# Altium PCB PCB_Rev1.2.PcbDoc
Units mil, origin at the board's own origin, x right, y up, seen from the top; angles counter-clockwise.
Board outline 1241 x 1329.22 mil, 4 copper layers (Top Layer, Layer 1, Layer 2, Bottom Layer), stack 69.556 mil thick; 69 components, 56 nets, 301 pads, 112 vias.
Unrouted connection lines stored in the file: 76.
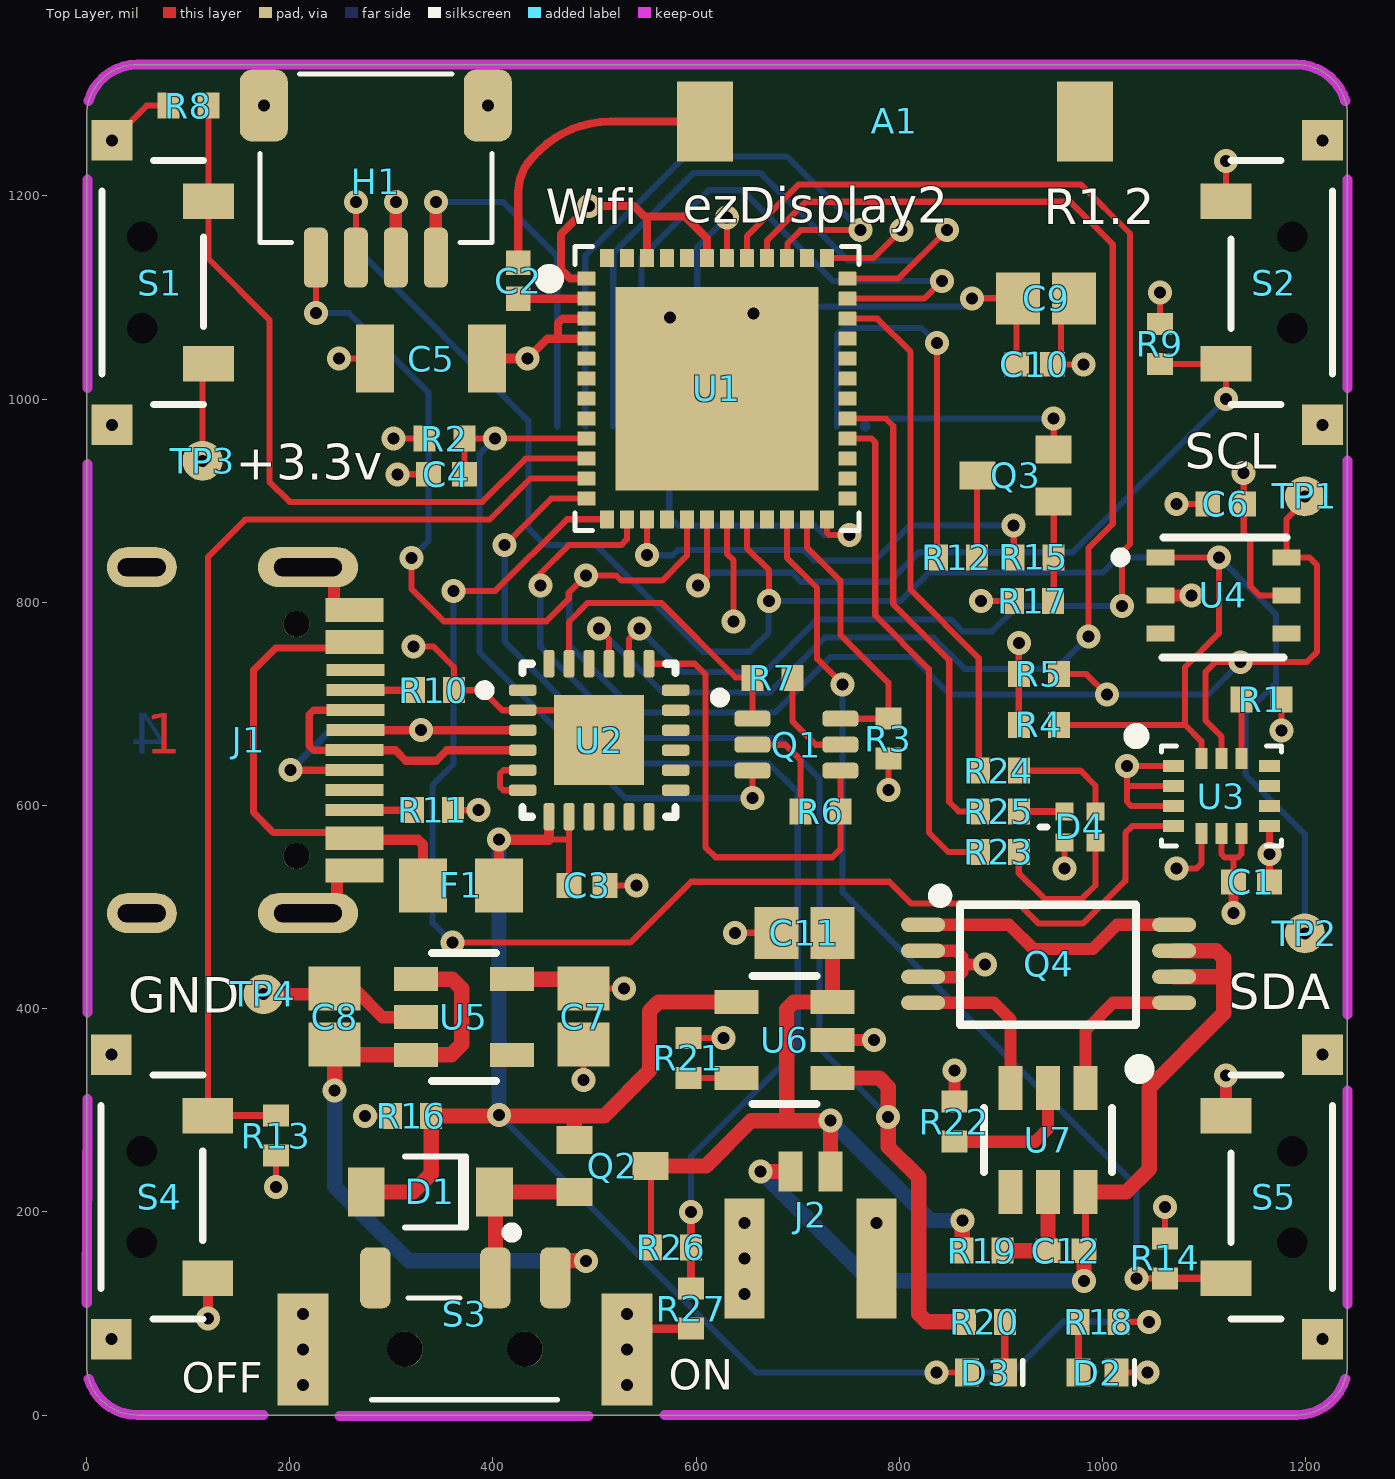
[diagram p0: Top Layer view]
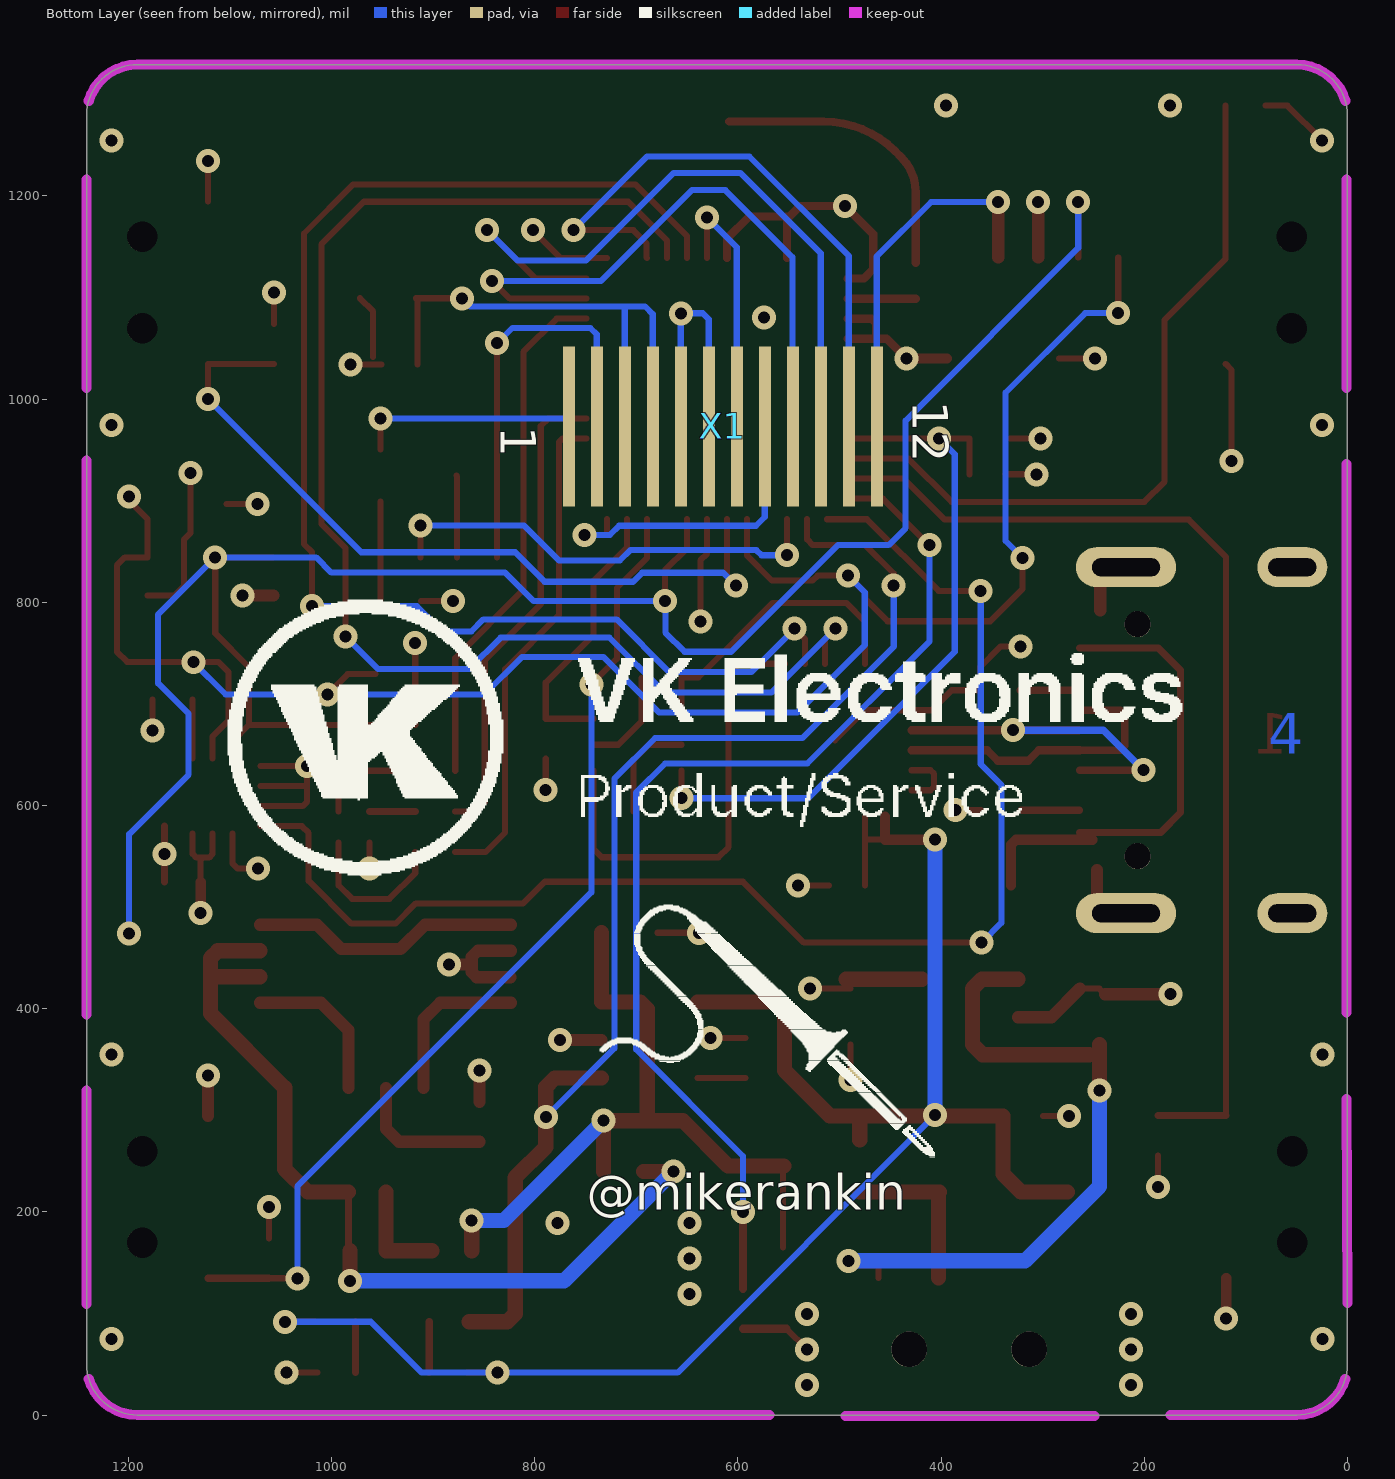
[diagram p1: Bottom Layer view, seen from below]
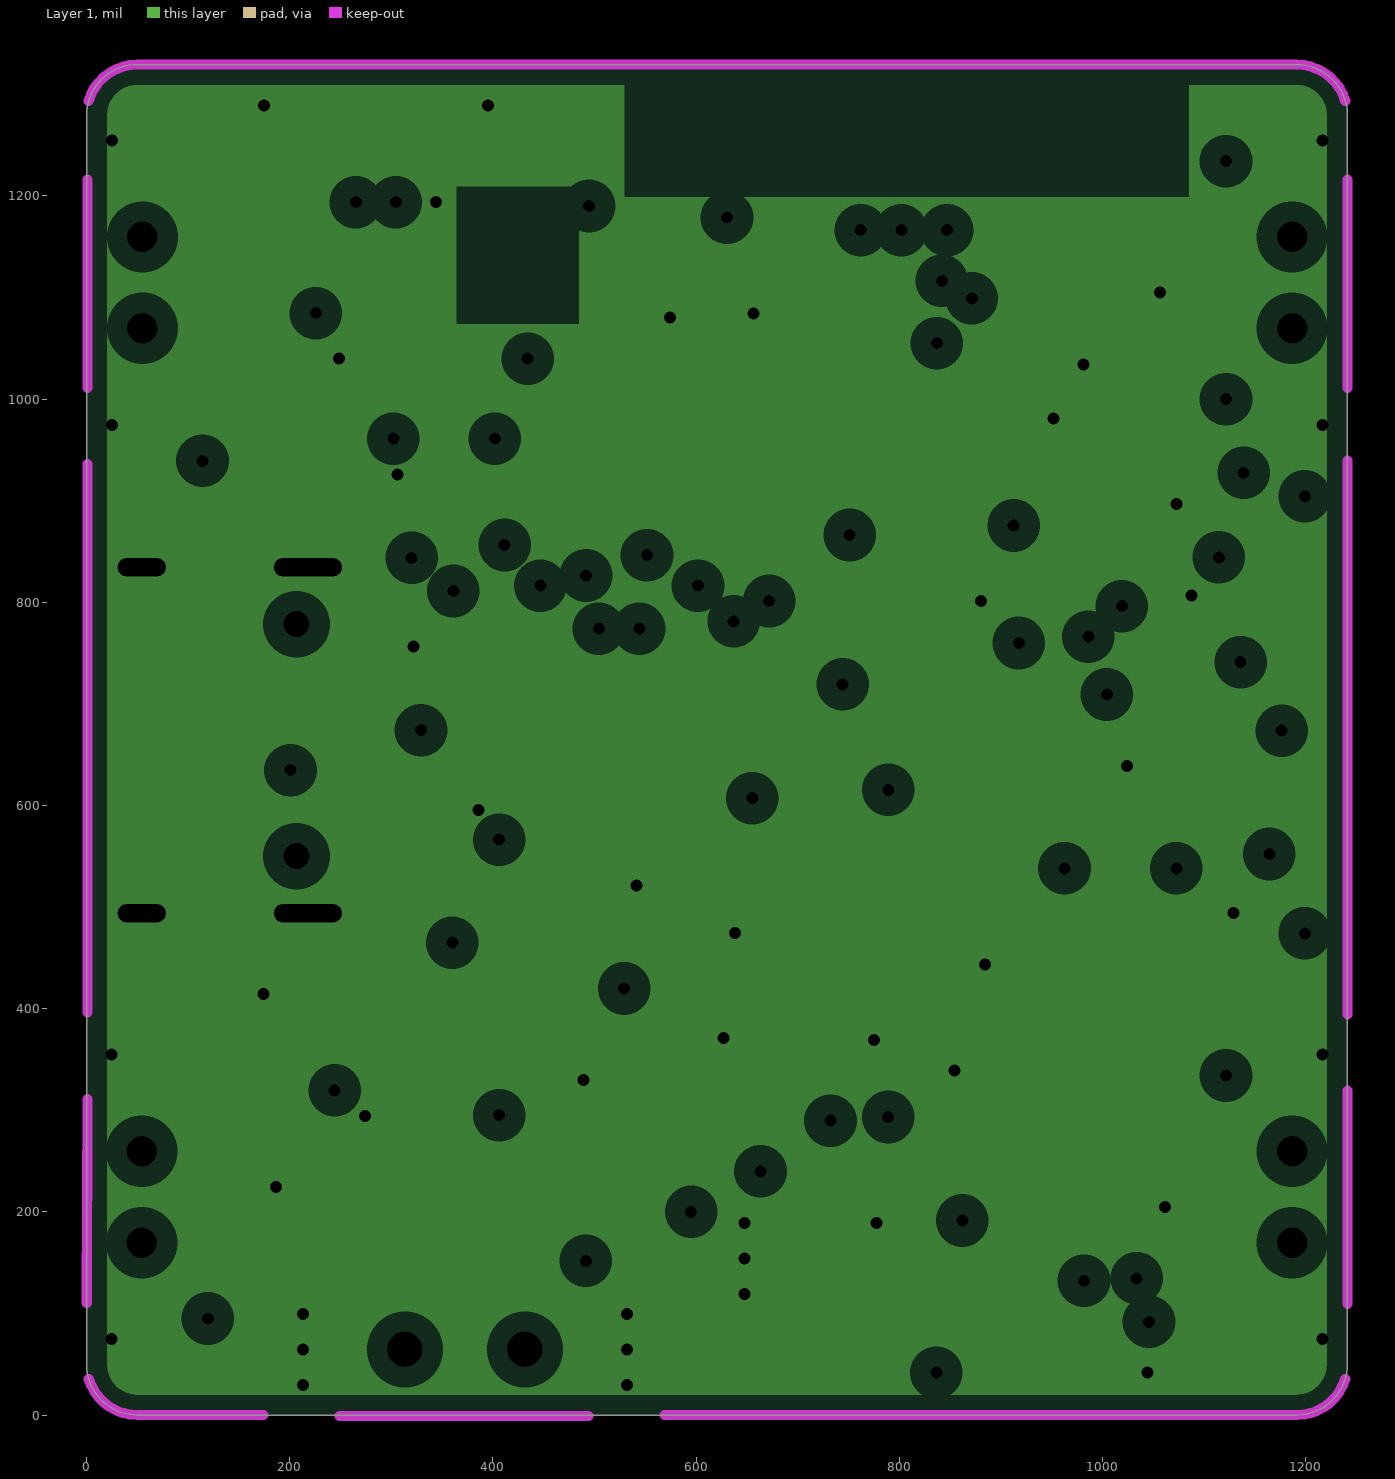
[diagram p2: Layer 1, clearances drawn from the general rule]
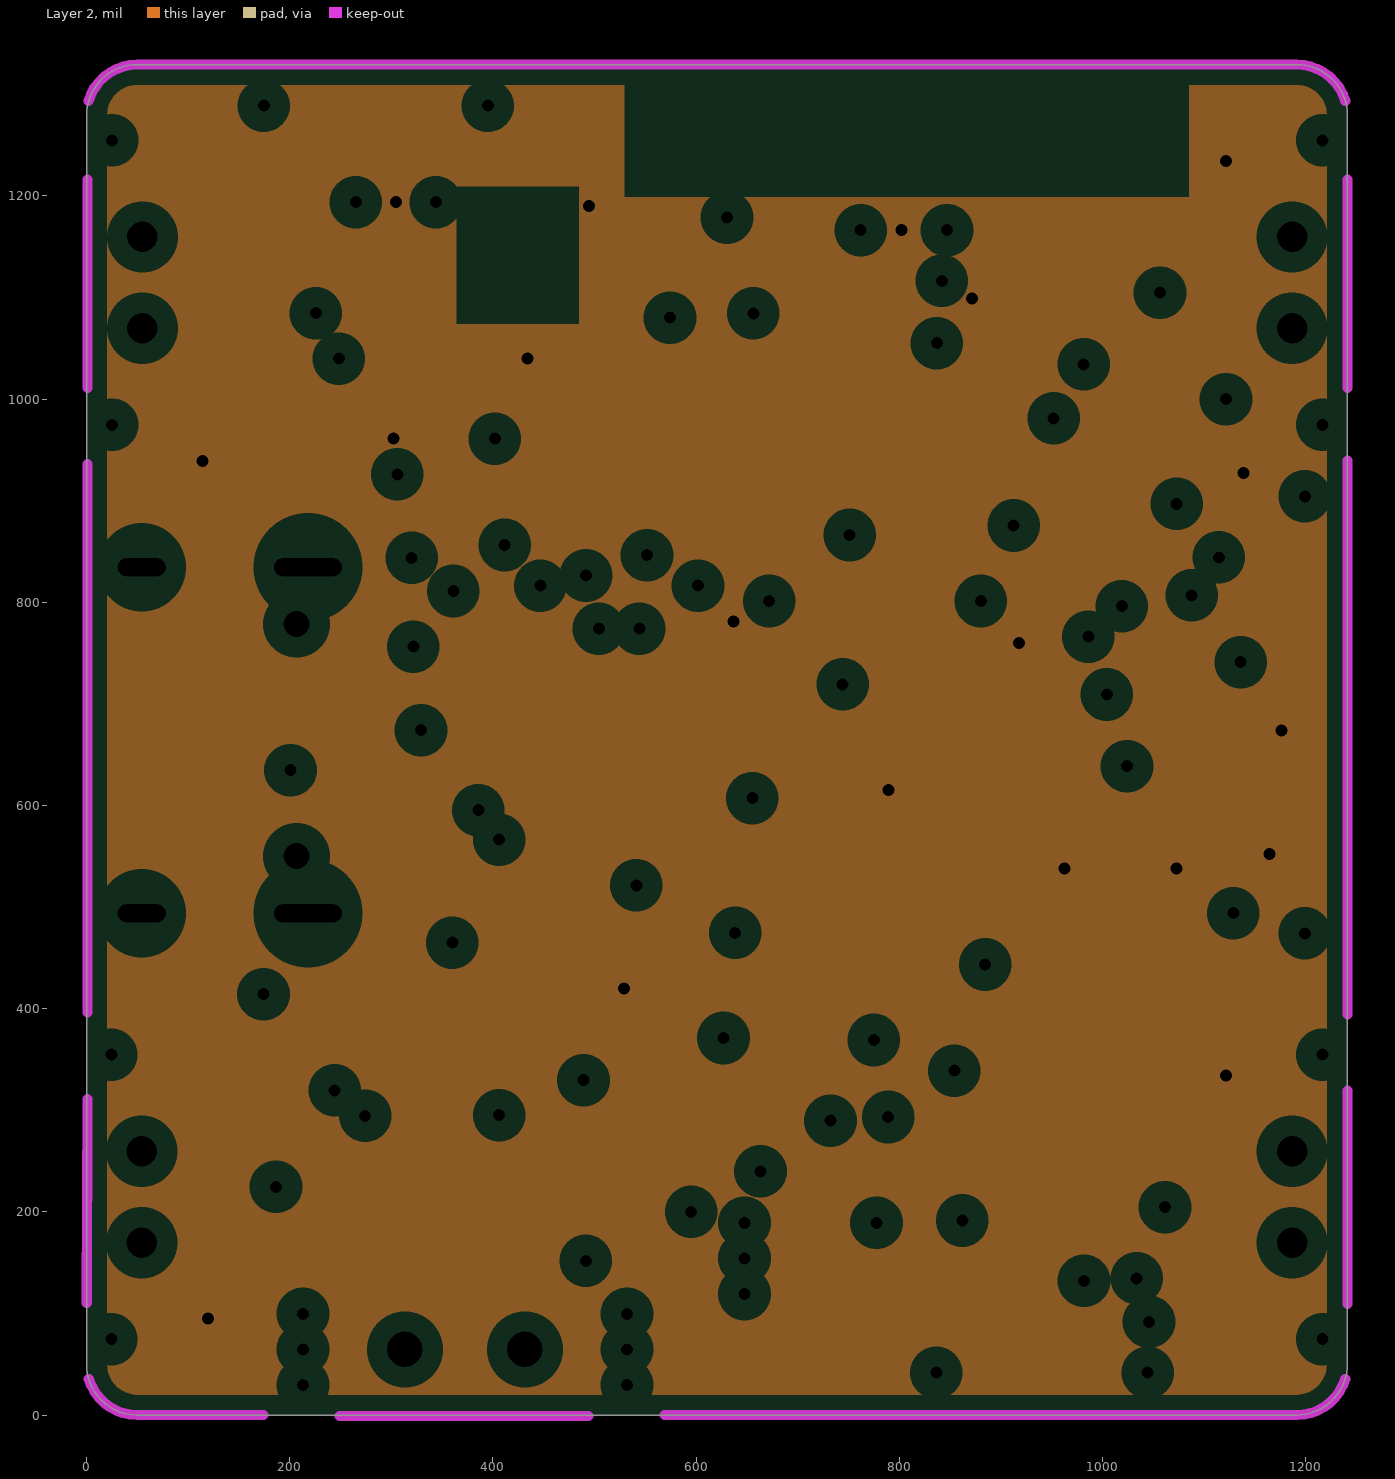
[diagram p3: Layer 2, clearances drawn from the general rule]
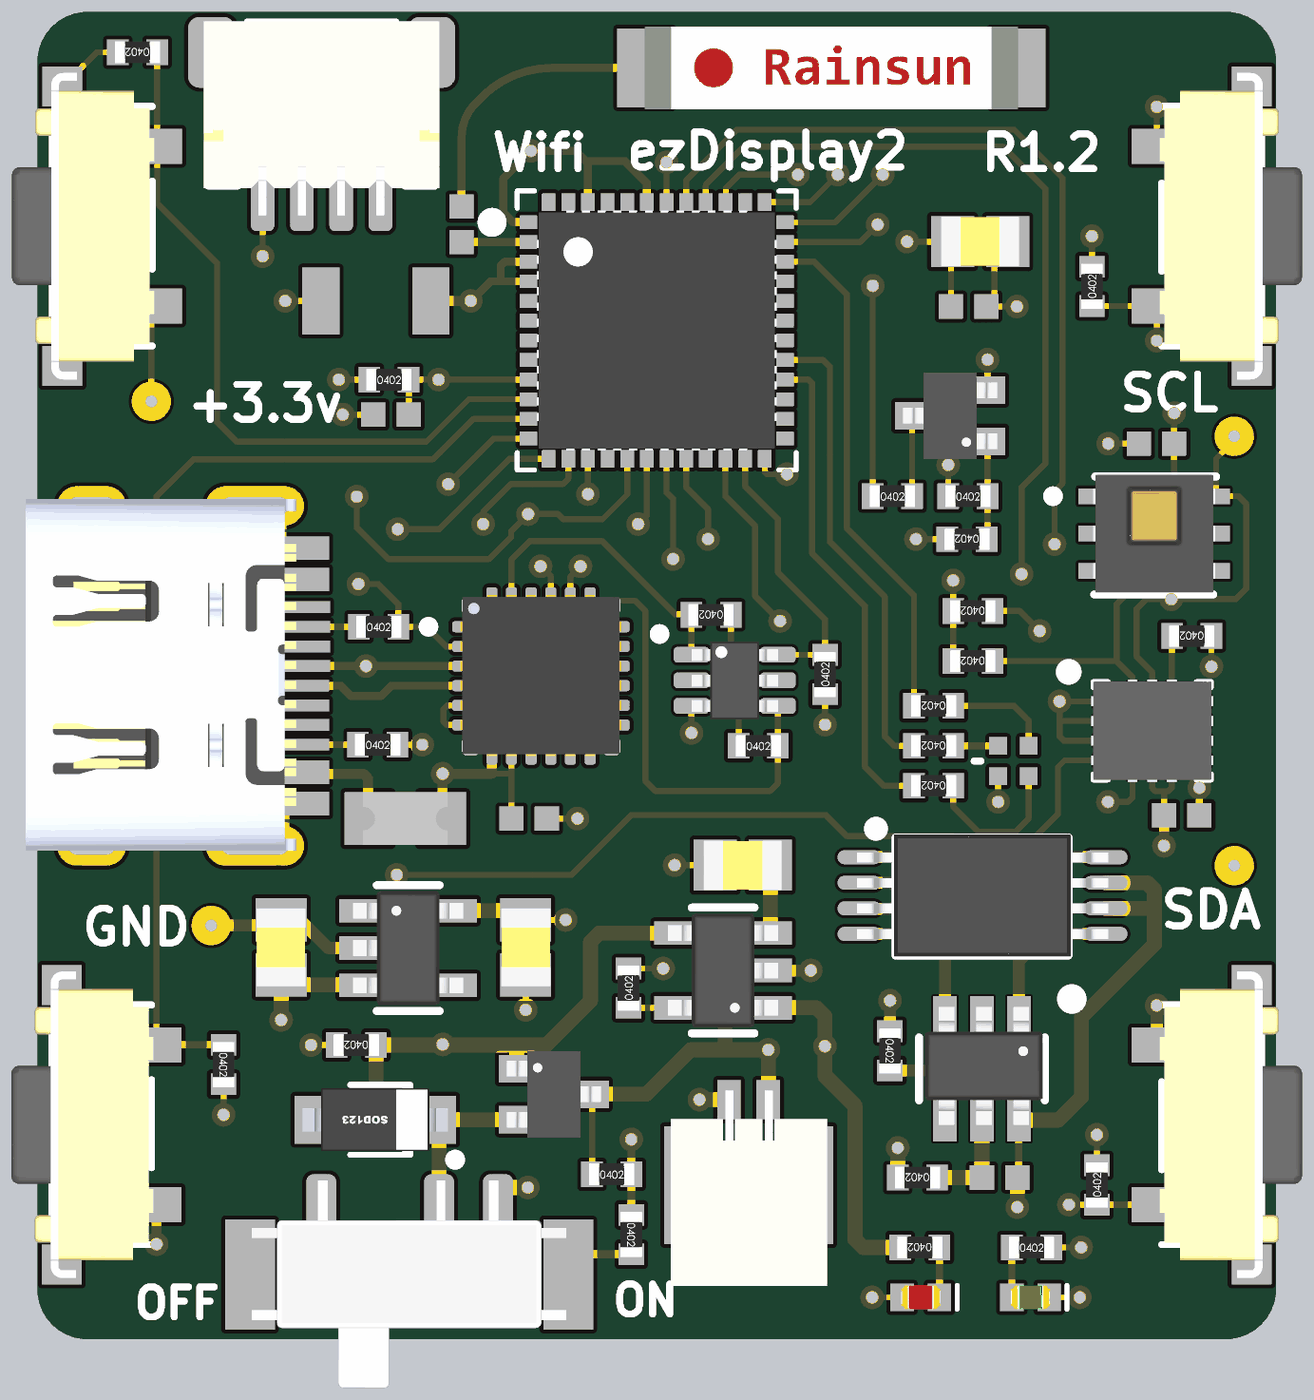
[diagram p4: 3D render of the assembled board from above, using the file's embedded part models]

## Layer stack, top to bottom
Top Solder: solder mask 0.4, Solder Resist, Dk 3.5
Top Layer: signal copper 1.4
Dielectric 2: prepreg 2.8, PP-006, Dk 4.1
Layer 1: plane copper 1.378, net GND
Dielectric 1: dielectric 58.4, FR-4, Dk 4.8
Layer 2: plane copper 1.378, net +3.3V
Dielectric 3: prepreg 2.8, PP-006, Dk 4.1
Bottom Layer: signal copper 1.4
Bottom Solder: solder mask 0.4, Solder Resist, Dk 3.5

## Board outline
0,50.22 0,1279.12 cw(c50,1279.22) 49.78,1329.22 50,1329.22 1190.9,1329.22 cw(c1191,1279.22) 1241,1279.44 1241,1279.22 1241,50.43 cw(c1190.67,50.33) 1190.89,0 50.1,0 cw(c50,50)

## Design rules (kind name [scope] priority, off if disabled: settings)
Clearance Clearance_U3 [All vs InComponent('U3')] p1: gap=5 ignorepadtopadclearanceinfootprint=FALSE
Clearance Clearance_Q1 [All vs InComponent('Q1')] p2: gap=5 ignorepadtopadclearanceinfootprint=FALSE
Clearance Clearance_U2 [All vs InComponent('U2')] p3: gap=5 ignorepadtopadclearanceinfootprint=FALSE
Clearance Clearance_J1 [All vs InComponent('J1')] p4: gap=5 ignorepadtopadclearanceinfootprint=FALSE
Clearance Clearance_U1 [All vs InComponent('U1')] p5: gap=5 ignorepadtopadclearanceinfootprint=FALSE
Clearance [All] p6: gap=10 ignorepadtopadclearanceinfootprint=FALSE except(0: Arc-Hole Track-Hole SMDPad-Hole THPad-Hole Via-Hole Fill-Hole Poly-Hole Region-Hole Text-Hole)
MinimumSolderMaskSliver [All] p1: minsoldermaskwidth=1
PlaneClearance [All] p1: clearance=20
PlaneConnect PlaneConnect_VIA [(IsVia)] p1: planeconnectstyle=Direct reliefexpansion=20 reliefentries=4 reliefconductorwidth=10 reliefairgap=10
PlaneConnect [All] p2: planeconnectstyle=Relief reliefexpansion=20 reliefentries=4 reliefconductorwidth=10 reliefairgap=10
PolygonConnect [All] p1: connectstyle=Relief reliefconductorwidth=10 reliefentries=4 polygonreliefangle="90 Angle" airgapwidth=10
RoutingVias [All] p1: holewidth=28 width=50 viastyle="Through Hole" minholewidth=28 minwidth=50 maxholewidth=28 maxwidth=50
SilkToSolderMaskClearance [IsPad] p1: minsilkscreentomaskgap=3 clearancetoexposedcopper=TRUE
SolderMaskExpansion [All] p1: expansion=4 istentingtop=FALSE
Width [All] p1: maxlimit=15 minlimit=6 preferedwidth=6
26 further rules are at their usual default settings.

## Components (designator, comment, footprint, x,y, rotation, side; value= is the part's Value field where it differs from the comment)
A1 "Antenna_Chip" AN9520-245 795.45,1273.22 r270 top value="Chip Antenna"
C1 "0.1uF" CAPC1005X56N 1146.43,524.7 r180 top
C2 "1.5pF" CAPC1005X56N 424.91,1116.52 r90 top
C3 "1uF" CAPC1005X56N 492.67,521.32 r0 top
C4 "0.1uF" CAPC1005X56N 354.19,926.01 r180 top
C5 "100uF" CAPC3216X160L 339.02,1039.81 r180 top
C6 "0.1uF" CAPC1005X56N 1121.19,896.82 r180 top
C7 "10uF" CAPC2012X140N 489.14,392.25 r270 top
C8 "10uF" CAPC2012X140N 244.14,392.25 r90 top
C9 "10uF" CAPC2012X140N 944.46,1099.22 r0 top
C10 "0.1uF" CAPC1005X56N 933,1034.22 r0 top
C11 "10uF" CAPC2012X140N 706.58,474.7 r180 top
C12 "0.1uF" CAPC1005X56N 964.03,161.82 r0 top
D1 "MBR0520" SOD123 338.45,219.67 r180 top
D2 "Green Led" LED1005X40N-Green 995.02,41.82 r180 top
D3 "Red Led" LED1005X40N-Red 885.02,41.82 r180 top
D4 "RGB" FC-B1010RGBT-HG 977.78,578.97 r180 top value="RGB Led"
F1 "TLC-PSMD050" PTC2012X70L 368.6,521.32 r180 top
H1 "QWiiC" SM04B-SRSS-TB 284.67,1214 r180 top
J1 "USB-C" TYPE-C-31-M-12 62.17,493.95 r270 top locked
J2 "CON2" JST_Micro_2PIN 712.57,239.85 r0 top locked value="Batt Con"
Q1 "BC847S" SOT65P210X110-6N 698.59,658.83 r0 top
Q2 "LP1480WT1G" SC-70 517.4,245.26 r0 top value="P-CH Mosfet"
Q3 "MMST3904" SC-70 914.5,924.81 r180 top
Q4 "FS8205A" "TSOP65P490X110-8N WIDE" 946.9,444.22 r0 top locked
R1 "10K" "RESC1005X40L (0402 FOOTPRINT)" 1156.58,704.22 r180 top
R2 "10K" "RESC1005X40L (0402 FOOTPRINT)" 352.22,961.01 r0 top
R3 "10K" "RESC1005X40L (0402 FOOTPRINT)" 789.1,665.72 r90 top
R4 "4.7K" "RESC1005X40L (0402 FOOTPRINT)" 937.21,679.22 r180 top
R5 "4.7K" "RESC1005X40L (0402 FOOTPRINT)" 937.21,729.22 r180 top
R6 "10K" "RESC1005X40L (0402 FOOTPRINT)" 722.21,594.22 r0 top
R7 "10K" "RESC1005X40L (0402 FOOTPRINT)" 674.97,725.4 r180 top
R8 "10K" "RESC1005X40L (0402 FOOTPRINT)" 100.22,1288.81 r180 top
R9 "10K" "RESC1005X40L (0402 FOOTPRINT)" 1056.45,1054.36 r90 top
R10 "5.1K" "RESC1005X40L (0402 FOOTPRINT)" 341.87,713.44 r0 top
R11 "5.1K" "RESC1005X40L (0402 FOOTPRINT)" 340.88,595.33 r0 top
R12 "22R" "RESC1005X40L (0402 FOOTPRINT)" 856.58,844.22 r0 top
R13 "10K" "RESC1005X40L (0402 FOOTPRINT)" 186.45,274.99 r270 top
R14 "10K" "RESC1005X40L (0402 FOOTPRINT)" 1061.45,154.36 r90 top
R15 "1K" "RESC1005X40L (0402 FOOTPRINT)" 932.21,844.22 r0 top
R16 "100K" "RESC1005X40L (0402 FOOTPRINT)" 319.46,294.47 r180 top
R17 "10K" "RESC1005X40L (0402 FOOTPRINT)" 931.31,801.22 r180 top
R18 "22K" "RESC1005X40L (0402 FOOTPRINT)" 996,91.82 r0 top
R19 "100R" "RESC1005X40L (0402 FOOTPRINT)" 881.63,161.82 r180 top
R20 "4.7K" "RESC1005X40L (0402 FOOTPRINT)" 884.03,91.82 r180 top
R21 "4.7K" "RESC1005X40L (0402 FOOTPRINT)" 592.27,351.51 r90 top
R22 "1K" "RESC1005X40L (0402 FOOTPRINT)" 854.14,288.75 r270 top
R23 "1K" "RESC1005X40L (0402 FOOTPRINT)" 897.84,554.22 r180 top
R24 "1K" "RESC1005X40L (0402 FOOTPRINT)" 897.84,634.22 r180 top
R25 "1K" "RESC1005X40L (0402 FOOTPRINT)" 897.84,594.22 r180 top
R26 "100K" "RESC1005X40L (0402 FOOTPRINT)" 575.31,165 r0 top
R27 "100K" "RESC1005X40L (0402 FOOTPRINT)" 595,104.69 r270 top
S1 "Push" 122514 100,1114.67 r270 top value="Button R/A"
S2 "Push" 122514 1141.45,1114.67 r90 top value="Button R/A"
S3 "SWITCH SLIDE" K3-1296S-E1 372.39,100.1 r0 top
S4 "Push" 122514 99.35,214.67 r270 top value="Button R/A"
S5 "Push" 122514 1141.45,214.67 r90 top value="Button R/A"
TP1 "Test Point, 1mm Top Layer" TP100TL#1 1319.1,859.22 r0 top
TP2 "Test Point, 1mm Top Layer" TP100TL#2 1179.1,444.22 r0 top
TP3 "Test Point, 1mm Top Layer" TP100TL#3 1374.1,454.22 r0 top
TP4 "Test Point, 1mm Top Layer" TP100TL#4 1333,104.22 r0 top
U1 "ESP32-PICO-D4" "QFN48_NEWEST 0.5mm pitch" 620.45,1010.22 r0 top locked
U2 "CP2104N" 24-QFN 504.48,664.22 r0 top
U3 "LSM6DS3TR" LSM6DS3 1116.9,609.22 r0 top
U4 "HDC1080DMBT" HDC1080 1118.91,806.82 r0 top
U5 "HT7833" SOT95P280X144-5N 371.43,391.62 r0 top
U6 "MCP73831T-2ACI/OT" SOT95P280X144-5N 686.95,369.22 r180 top value=MCP73831T-2ACI
U7 "DW01A" SOT95P280X130-6N 946.32,270.64 r270 top
X1 "TFT_1.54\"" "TFT_GLASS 1.54 INCH" 614.84,973.19 r270 bottom locked

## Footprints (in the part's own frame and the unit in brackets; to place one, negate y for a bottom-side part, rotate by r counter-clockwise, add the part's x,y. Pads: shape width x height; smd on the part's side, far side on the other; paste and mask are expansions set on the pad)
24-QFN [mm] "24-QFN Exposed Pad (4x4)"
  rrect50% 0.69x0.28 smd: 1(-1.912,1.25) 2(-1.912,0.75) 3(-1.912,0.25) 4(-1.912,-0.25) 5(-1.912,-0.75) 6(-1.912,-1.25) 13(1.913,-1.25) 14(1.913,-0.75) 15(1.913,-0.25) 16(1.913,0.25) 17(1.913,0.75) 18(1.913,1.25)
  rrect50% 0.28x0.69 smd: 7(-1.25,-1.913) 8(-0.75,-1.913) 9(-0.25,-1.913) 10(0.25,-1.913) 11(0.75,-1.913) 12(1.25,-1.913) 19(1.25,1.913) 20(0.75,1.913) 21(0.25,1.913) 22(-0.25,1.913) 23(-0.75,1.913) 24(-1.25,1.913)
  rect 2.25x2.25 smd paste-1.3: 25(0,0)
  silkscreen extent -2.99,-1.91 1.91,1.91, body extent -2.05,-2.04 2.05,2.06, height 1.08
122514 [mil] "DX BUTTON SWITCH R/A"
  rect 35x50 smd: 1(-80,20) 2(80,20)
  rect 40x40 smd: 3(-140,-75) 4(140,-75)
  round 29 hole 30 unplated: ""(-45,-45) ""(45,-45)
  silkscreen extent -120,-85 120,15, body extent -154,-126 154,17, height 134
AN9520-245 [mm] "Antenna Chip"
  rect 2x1.4 smd: 1(0,-4.75) ""(0,4.75)
  body extent -1.05,-4.75 1.05,4.75, height 1.05
CAPC1005X56N [mm] "Chip Capacitor, 2-Leads, Body 1.0x0.5mm, IPC Medium Density (0402 ceramic)"
  rect 0.62x0.62 smd: 1(-0.45,0) 2(0.45,0)
  body extent -0.55,-0.3 0.55,0.3, height 0.6
CAPC2012X140N [mm] "Chip Capacitor, 2-Leads, Body 2.0x1.3mm, IPC Medium Density (0805 ceramic)"
  rect 1.1x1.3 smd: 1(-0.7,0) 2(0.7,0)
  body extent -1,-0.62 1,0.63, height 1.24
CAPC3216X160L [mm] "Chip Capacitor, 2-Leads, Body 3.2x1.6mm, IPC Least Density(C1206)"
  rect 0.95x1.7 smd: 1(-1.4,0) 2(1.4,0)
  body extent -1.7,-0.9 1.7,0.9, height 1.9
FC-B1010RGBT-HG [mm] "LED,RGB,SMD,RoHS"
  rect 0.45x0.45 smd: 1(0.387,0.388) 2(0.387,-0.387) 3(-0.387,-0.387) 4(-0.387,0.388)
  silkscreen extent 0.83,0 1,0, body extent -0.53,-0.55 0.53,0.58, height 0.9
HDC1080 [mm] "Temp/Humidity Sensor"
  rect 0.7x0.4 smd mask+0.076: 1(-1.575,0.95) 2(-1.575,0) 3(-1.575,-0.95) 5(1.575,0) 6(1.575,0.95)
  rect 0.7x0.4 smd paste+0 mask+0.076: 4(1.575,-0.95)
  silkscreen extent -2.7,-1.55 1.57,1.45, body extent -1.55,-1.5 1.55,1.5, height 0.85
JST_Micro_2PIN [mm]
  rect 0.6x1 smd: 1(0.5,0) 2(-0.5,0)
  rect 1x3 smd: ""(-1.65,-2.175) ""(1.65,-2.175)
  body extent -1.99,-4.74 2,0.24, height 2.9
K3-1296S-E1 [mil] "Toggle Switches SMD RoHS"
  rrect50% 30x60 smd: 1(89.06,35) 2(30,35) 3(-88.11,35)
  rect 50x110 smd: 4(-159.45,-35.43) 4(159.45,-35.43)
  round 35 hole 35 unplated: ""(-59.06,-35.43) ""(59.06,-35.43)
  silkscreen extent -92,-85 91,15, body extent -157,-149 158,59, height 60
LED1005X40N-Green [mm] "Chip LED 2-Leads, Body 1.0x0.5mm, (0402)"
  rect 0.6x0.7 smd: 1(-0.475,0) 2(0.475,0)
  silkscreen extent -0.92,-0.3 -0.92,0.3, body extent -0.5,-0.3 0.5,0.3, height 0.2
LED1005X40N-Red [mm] "Chip LED 2-Leads, Body 1.0x0.5mm, (0402)"
  rect 0.6x0.7 smd: 1(-0.475,0) 2(0.475,0)
  silkscreen extent -0.92,-0.3 -0.92,0.3, body extent -0.5,-0.3 0.5,0.3, height 0.2
LSM6DS3 [mm] "IMU ACCEL/GYRO I2C/SPI 14VFLGA"
  rect 0.525x0.3 smd mask+0.076: 1(-1.2,0.75) 2(-1.2,0.25) 3(-1.2,-0.25) 4(-1.2,-0.75) 8(1.2,-0.75) 9(1.2,-0.25) 10(1.2,0.25) 11(1.2,0.75)
  rect 0.3x0.525 smd mask+0.076: 5(-0.5,-0.94) 6(0,-0.94) 7(0.5,-0.94) 12(0.5,0.94) 13(0,0.94) 14(-0.5,0.94)
  silkscreen extent -2.32,-1.25 1.5,1.7, body extent -1.55,-1.3 1.55,1.3, height 0.86
PTC2012X70L [mm] "Chip Fuse, 2-Leads, Body 2.0x1.3mm, IPC Medium Density (0805)"
  rect 1.2x1.35 smd: 1(-0.95,0) 2(0.95,0)
  body extent -1.07,-0.67 1.08,0.68, height 0.66
"QFN48_NEWEST 0.5mm pitch" [mm] "QFN, 48-Leads, Body 7x7mm, Pitch 0.5mm, IPC Medium Density"
  rrect9% 0.45x0.35 smd: 1(-3.265,2.75) 2(-3.265,2.25) 3(-3.265,1.75) 4(-3.265,1.25) 5(-3.265,0.75) 6(-3.265,0.25) 7(-3.265,-0.25) 8(-3.265,-0.75) 9(-3.265,-1.25) 10(-3.265,-1.75) 11(-3.265,-2.25) 12(-3.265,-2.75) 25(3.265,-2.75) 26(3.265,-2.25) 27(3.265,-1.75) 28(3.265,-1.25) 29(3.265,-0.75) 30(3.265,-0.25) 31(3.265,0.25) 32(3.265,0.75) 33(3.265,1.25) 34(3.265,1.75) 35(3.265,2.25) 36(3.265,2.75)
  rrect9% 0.35x0.45 smd: 13(-2.75,-3.265) 14(-2.25,-3.265) 15(-1.75,-3.265) 16(-1.25,-3.265) 17(-0.75,-3.265) 18(-0.25,-3.265) 19(0.25,-3.265) 20(0.75,-3.265) 21(1.25,-3.265) 22(1.75,-3.265) 23(2.25,-3.265) 24(2.75,-3.265) 37(2.75,3.265) 38(2.25,3.265) 39(1.75,3.265) 40(1.25,3.265) 41(0.75,3.265) 42(0.25,3.265) 43(-0.25,3.265) 44(-0.75,3.265) 45(-1.25,3.265) 46(-1.75,3.265) 47(-2.25,3.265) 48(-2.75,3.265)
  rect 5.08x5.08 smd paste-4: 49(0,0)
  silkscreen extent -4.37,-3.55 3.55,3.55, body extent -3.05,-3.05 3.05,3.05, height 0.9
"RESC1005X40L (0402 FOOTPRINT)" [mm] "Chip Resistor, 2-Leads, Body 1.0x0.5mm, IPC Medium Density (0402)"
  rect 0.55x0.65 smd: 1(-0.5,0) 2(0.5,0)
  body extent -0.57,-0.27 0.58,0.28, height 0.41
SC-70 [mm] "SOT23, 3-Leads, Body 2x1.25mm, Pitch 0.65mm"
  rect 0.9x0.7 smd: 1(-0.95,0.65) 2(-0.95,-0.65) 3(0.95,0)
  body extent -1.2,-1.1 1.2,1.1, height 1
SM04B-SRSS-TB [mm] "CONN HEADER 4POS .100 R/A QWIIC"
  rrect50% 0.6x1.5 smd: 1(1.5,1.9) 2(0.5,1.9) 3(-0.5,1.9) 4(-1.5,1.9)
  rrect50% 1.2x1.8 smd: 5(-2.8,-1.9) 5(2.8,-1.9)
  silkscreen extent -2.9,-2.69 2.9,1.52, body extent -3,-2.69 3,2.26, height 3.25
SOD123 [mil] "Molded Diode, 2-Leads, Body 2.85x1.8mm, IPC Medium Density (SOD123)"
  rect 36x48 smd: 1(-63,0) 2(63,0)
  silkscreen extent -85,-35 25,45, body extent -73,-31 73,31, height 50
SOT65P210X110-6N [mm] "SC70, 6-Leads, Body 2.4x2.2mm (max), Pitch 0.65mm, IPC Medium Density"
  rrect50% 0.9x0.4 smd mask+0.076: 1(-1.1,0.675) 2(-1.1,0.025) 3(-1.1,-0.625) 4(1.1,-0.625) 5(1.1,0.025) 6(1.1,0.675)
  silkscreen extent -2.04,1.08 -1.79,1.33, body extent -1.1,-0.97 1.1,1.01, height 0.99
SOT95P280X130-6N [mm] "SOT23, 6-Leads, Body 3.0x3.0mm (max), Pitch 0.95mm, IPC Medium Density"
  rect 1.1x0.6 smd mask+0.051: 1(-1.3,0.94) 2(-1.3,0) 3(-1.3,-0.94) 4(1.3,-0.94) 5(1.3,0) 6(1.3,0.94)
  silkscreen extent -1.9,-1.6 0.8,2.41, body extent -1.57,-1.45 1.43,1.55, height 1.45
SOT95P280X144-5N [mm] "SOT23, 5-Leads, Body 3.1x3.0mm (max), Pitch 0.95mm, IPC Medium Density (RFMD SOT23-5)"
  rect 1.1x0.6 smd: 1(-1.2,0.95) 2(-1.2,0) 3(-1.2,-0.95) 4(1.2,-0.95) 5(1.2,0.95)
  silkscreen extent -0.8,-1.6 0.8,1.6, body extent -1.4,-1.45 1.4,1.45, height 1.45
"TFT_GLASS 1.54 INCH" [mm] "TFT_GLASS 1.54 INCH"
  rect 4x0.3 smd: 1(0,-3.85) 2(0,-3.15) 3(0,-2.45) 4(0,-1.75) 5(0,-1.05) 6(0,-0.35) 7(0,0.35) 8(0,1.05) 9(0,1.75) 10(0,2.45) 11(0,3.15) 12(0,3.85)
  Top Layer lines w0.254: 0,-3.85 0,-3.85
  body extent -9,-15.91 24.73,15.59, height 2
TP100TL#1 [mil] "Test Point"
  round 39.37 smd paste-19.68 mask+3: 1(-120,45)
TP100TL#2 [mil] "Test Point"
  round 39.37 smd paste-19.68 mask+3: 1(20,30)
TP100TL#3 [mil] "Test Point"
  round 39.37 smd paste-19.68 mask+3: 1(-1260,485)
TP100TL#4 [mil] "Test Point"
  round 39.37 smd paste-19.68 mask+3: 1(-1158.9,310)
"TSOP65P490X110-8N WIDE" [mil] "TSOP, Wide, 8-Leads, Body 464x3.0mm (max), Pitch 0.65mm, IPC Medium Density"
  oval 43.5x14 smd mask+3: 1(-123.52,38.39) 2(-123.52,12.8) 3(-123.52,-12.8) 4(-123.52,-38.39) 5(123.52,-38.39) 6(123.52,-12.8) 7(123.52,12.8) 8(123.52,38.39)
  silkscreen extent -113,-60 86,73, body extent -126,-61 126,61, height 43
TYPE-C-31-M-12 [mm] "USB-C Connector"
  oval 1x2.5 hole 0.45 slot 1.7 at 90 deg: 1(-8.65,3.955) 1(0,3.955)
  oval 1x1.75 hole 0.45 slot 1.2 at 90 deg: 1(-8.65,-0.2) 1(0,-0.2)
  rect 0.3x1.45 smd: A1(-7.726,5.119) A4(-6.926,5.117) A5(-5.575,5.142) A6(-4.575,5.142) A7(-4.075,5.117) A8(-3.075,5.117) A9(-1.727,5.117) A12(-0.924,5.117) B1(-1.224,5.117) B4(-2.021,5.117) B5(-2.575,5.117) B6(-3.575,5.117) B7(-5.075,5.142) B8(-6.075,5.142) B9(-6.626,5.117) B12(-7.426,5.119)
  round 0.65 hole 0.65 unplated: ""(-7.225,3.667) ""(-1.425,3.667)
  body extent -8.82,-1.89 0.12,5.01, height 3.31

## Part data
A1: "Antenna Chip 2.4Gig", LCSC_Part_Number=C99665, Manufacturer=Rainsun
C1 C4 C6 C10 C12: library part CAP_0402, "CAP 0.1uF 0402", LCSC_Part_Number=C344190, Manufacturer=CCTC
C2: library part CAP_0402, "CAP 1.5pF 0402", LCSC_Part_Number=C147344, Manufacturer=Dafron
C3: library part CAP_0603, "CAP 1uF 16V 0402", LCSC_Part_Number=C83063, Manufacturer=Walsin
C5: library part CAP_1206, "CAP 100uF 6.3V 1206", LCSC_Part_Number=C87164, Manufacturer="Taiyo Yuden"
C7 C8 C9 C11: library part CAP_0805, "CAP 10uF 0805", LCSC_Part_Number=C307520, Manufacturer=Samsung
D1: library part MBR0520-TP, "DIODE SCHOTTKY 20V 500MA SOD123", LCSC_Part_Number=C475717, Manufacturer=CJ
D2: library part LED_0402_SMALL_GREEN, "LED Green 0402", LCSC_Part_Number=C74338, Manufacturer=Lite-On
D3: library part LED_0402_SMALL_Red, "LED RED 0402", LCSC_Part_Number=C364556, Manufacturer=Lite-On
D4: library part FC-B1010RGBT-HG, "LED,RGB LED,SMD,RoHS", LCSC_Part_Number=C158099, Manufacturer=Foshan
F1: library part PTC_FUSE, "PTC FUSE 500mA hold, 1A trip 0805 SMD", LCSC_Part_Number=C261942, Manufacturer=TLC
H1: library part SM04B-SRSS-TB, "CONN HEADER 4POS .100 R/A QWIIC", LCSC_Part_Number=C160404, Manufacturer=JST, PartNumber=SM04B-SRSS-TB(LF)(SN)
J1: "CONN RECPT USB-C", LCSC_Part_Number=C165948, Manufacturer=KHE
J2: library part JST_Micro_CONN_2PIN, "MIcro CONN 2POS 1.0MM SMT R/A", LCSC_Part_Number=C395299, Manufacturer=JUSHUO
Q1: "TRANS 2NPN 44V 0.1A SC-70-6", LCSC_Part_Number=C148112, Manufacturer=Changjiang
Q2: "MOSFET P-CH 20V 1.4A SC-70", LCSC_Part_Number=C172434, Manufacturer=LRC
Q3: "TRANSISTOR NPN GP 40V SC-70", LCSC_Part_Number=C54879, Manufacturer=Changjiang
Q4: "MOSFET 2N-CH 20V 6A TSSOP-8L", LCSC_Part_Footprint=TSSOP-8L, LCSC_Part_Number=C16052, Manufacturer=Fortune
R1 R2 R3 R6 R7 R8 R9 R13 R14 R17: library part RES_0402, "RES 10K 0402", LCSC_Part_Number=C258091, Manufacturer=Guangdong
R4 R5: library part RES_0402, "RES 4.7K 0402", LCSC_Part_Number=C25900, Manufacturer=Uni-Royal
R10 R11: library part RES_0603, "RES 5.1K 0402", LCSC_Part_Number=C325521, Manufacturer=TyoHM
R12: library part RES_0402, "RES 22R 0402", LCSC_Part_Number=C25092, Manufacturer=Uniroyal
R15 R22 R23 R24 R25: library part RES_0402, "RES 1K 0402", LCSC_Part_Number=C106235, Manufacturer=Yageo
R16 R26 R27: library part RES_0603, "RES 100K 0402", LCSC_Part_Number=C25741, Manufacturer="Uniroyal Elec"
R18: library part RES_0603, "RES 22K 0402", LCSC_Part_Number=C100310, Manufacturer="LIZ Elec"
R19: library part RES_0603, "RES 100R 0402", LCSC_Part_Number=C106232, Manufacturer=Yageo
R20 R21: library part RES_0603, "RES 4.7K 0402", LCSC_Part_Number=C25900, Manufacturer=Uni-Royal
S1 S2 S4 S5: library part "Side Actuated Button R/A", "Side Actuated Button R/A", LCSC_Part_Number=C319377, Manufacturer=HYP
S3: library part K3-1296S-E1, "SWITCH SLIDE SMD", LCSC_Part_Number=C128955, Manufacturer="Korean Hroparts Elec"
TP1 TP2 TP3 TP4: Manufacturer=N/A
U1: "RF Transceiver ICs QFN-48_7x7x05P RoHS", LCSC_Part_Number=C193707, Manufacturer=Espressif
U2: "IC BRIDGE USB TO UART 24QFN", LCSC_Part_Number=C47742, Manufacturer="Silicon Labs"
U3: library part "LSM6DS3 (obsolete)", "IMU ACCEL/GYRO I2C/SPI 14VFLGA", LCSC_Part_Number=C95230, Manufacturer="ST MICRO"
U4: "Humidity/Temperature Sensor", LCSC_Part_Number=C82227, Manufacturer="Texas Instruments"
U5: "IC LDO 3.3V 0.5A SOT23-5", LCSC_Part_Number=C164106, Manufacturer=Holtek
U6: "Charger IC Lithium-Ion/Polymer SOT23-5", LCSC_Part_Number=C424093, Manufacturer=Microchip
U7: "IC LITHIUM BATT PROTECT SOT-23-6L", LCSC_Part_Number=C351410, Manufacturer=PUOLOP
X1: library part "TFT_GLASS 1.54 INCH COLOR", "1.54 INCH TFT GLASS COLOR", Manufacturer=BuyDisplay

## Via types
v1: diameter 23.62, hole 11.81, Top Layer to Bottom Layer, tented both sides, 112 vias

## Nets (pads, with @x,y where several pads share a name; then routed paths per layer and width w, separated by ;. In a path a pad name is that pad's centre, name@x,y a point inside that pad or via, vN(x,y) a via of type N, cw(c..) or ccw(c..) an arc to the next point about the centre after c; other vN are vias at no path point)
+3.3V: C1.1 C5.1 C6.1 C7.1 C9.1 C10.1 D4.1 H1.3 R1.1 R2.1 R3.1 R4.2 R5.2 S1.2 S2.2 S4.2 S5.2 TP3.1 U1.1 U1.3 U1.4 U1.19 U1.37 U1.43 U1.46 U3.5 U3.8 U4.5 U5.5 X1.3 X1.4 | length 2011.1
  Top Layer w6: v1(114.1,939.22) 114.1,1028.77 S1.2 ; v1(301.91,961.01) R2.1 ; C7.1 v1(529.14,419.81) ; 549.14,1179.81 551.55,1179.81 ; U1.19 630.29,847.87 636.85,841.32 v1(636.85,781.32) ; U1.37 774.3,1138.77 v1(801.85,1166.32) ; v1(789.1,615.4) R3.1 ; v1(871.27,1099.22) C9.1 915.28,1097.61 C10.1 ; R4.2 R5.2 v1(917.53,759.85) ; v1(962.53,538.08) D4.1 ; v1(1072.53,538.08) 1092.53,538.08 1097.21,542.77 U3.5 ; S2.2 v1(1121.45,1234.22) ; v1(1138.91,927.45) C6.1 1138.91,868.05 1145.29,861.66 1145.29,815.83 1154.3,806.82 U4.5 ; v1(1176.27,673.59) R1.1
  Top Layer w7: C1.1 U3.8
  Top Layer w8: v1(434.14,1039.81) 453.76,1059.44 464.14,1059.44 ; U1.4 464.14,1059.44 ; U1.3 468.45,1079.12 464.14,1074.81 464.14,1059.44 ; U1.1 491.62,1118.77 475.84,1118.77 466.79,1127.82 466.79,1162.34 v1(494.53,1190.08) 538.87,1190.08 549.14,1179.81 ; U1.46 551.55,1177.4 ; 551.55,1179.81 588.8,1179.81 610.61,1158.01 U1.43
  Top Layer w10: v1(119.35,95.12) S4.2 ; C5.1 v1(434.14,1039.81)
  Top Layer w12: H1.3 v1(304.36,1193.81) ; S5.2 v1(1121.45,334.22)
  Top Layer w15: U5.5 C7.1@493.47,429.03
  Bottom Layer w6: X1.4 683.74,1083.66 691.39,1091.32 711.3,1091.32 ; X1.3 711.3,1091.32 ; v1(871.27,1099.22) 863.36,1091.32 711.3,1091.32
  other v1: 1164.14,552.2
BAT_MON: R26.2 R27.1 U1.12 | length 1076.2
  Top Layer w6: v1(411.55,856.32) 457.19,901.96 U1.12
  Top Layer w8: R27.1 R26.2 v1(595,200)
  Bottom Layer w6: v1(411.55,856.32) 411.55,761.32 531.55,641.32 671.55,641.32 700,612.87 700,360 595,255 v1(595,200)
BLUE: R23.2 U1.28 | length 491.7
  Top Layer w6: U1.28 772.68,961.01 776.2,957.5 776.2,787.13 829.1,734.22 829.1,573.41 848.29,554.22 R23.2
BUTTON_1: R8.1 S1.1 U1.10 | length 732.8
  Top Layer w6: R8.1 119.91,1194.76 S1.1 120,1137.92 179.91,1078.01 179.91,918.81 199.96,898.75 389.65,898.75 432.22,941.33 U1.10
BUTTON_2: R9.1 S2.1 U1.18 | length 771.7
  Top Layer w6: v1(601.85,816.32) 610.61,825.08 U1.18 ; R9.1 S2.1 v1(1121.45,999.97)
  Bottom Layer w6: v1(601.85,816.32) 614.57,829.03 694.29,829.03 703.1,820.22 790.1,820.22 819.1,849.22 970.7,849.22 v1(1121.45,999.97)
BUTTON_3: R13.1 S4.1 U1.11 | length 1021.4
  Top Layer w6: S4.1 119.35,844.47 156.2,881.32 396.55,881.32 436.88,921.64 U1.11
  Top Layer w7: S4.1 R13.1
BUTTON_4: R14.1 S5.1 U1.22 | length 977.5
  Top Layer w6: U1.22 689.35,843.82 719.1,814.06 719.1,744.22 v1(744.1,719.22) ; v1(1033.47,134.67) R14.1
  Top Layer w7: R14.1 S5.1
  Bottom Layer w6: v1(744.1,719.22) 744.1,514.51 1033.47,225.15 v1(1033.47,134.67)
CHG: R20.2 U1.14 U6.1 | length 1227.3
  Top Layer w6: v1@449.27,819.03 v1(446.55,816.32) 446.55,828.32 474.55,856.32 526.32,856.32 531.87,861.87 U1.14
  Top Layer w15: U6.1 780.24,331.82 789.02,323.03 v1(789.02,293.39) 789.02,263.75 819.14,233.63 819.14,99.7 827.02,91.82 R20.2
  Bottom Layer w6: v1(446.55,816.32) 446.55,756.32 536.55,666.32 681.55,666.32 721.55,626.32 721.55,360.86 v1(789.02,293.39)
D+: J1.A6 J1.B6 U2.3 | length 372.2
  Top Layer w7: v1(200.76,634.7) J1.B6
  Top Layer w8: J1.A6 v1(329.18,674.07) U2.3
  Bottom Layer w7: v1(200.76,634.7) 240.13,674.07 v1(329.18,674.07)
D-: J1.A7 J1.B7 U2.4 | length 298.2
  Top Layer w7: 219.18,689.3 219.18,658.48 223.28,654.38 J1.A7 ; 219.18,689.65 223.28,693.75 J1.B7
  Top Layer w8: J1.A7 303.87,654.38 314.18,644.07 344.18,644.07 354.5,654.38 U2.4
DC: U1.42 X1.7 | length 257.5
  Top Layer w6: U1.42 v1(630.29,1178.66)
  Bottom Layer w6: X1.7 601.06,1149.43 v1(630.29,1178.66)
DTR: Q1.1 R7.2 U2.23 | length 300.1
  Top Layer w6: U2.23 474.95,781.09 493.18,799.32 565.64,799.32 638.97,725.98 654.71,725.98 R7.2 Q1.1
EN: C4.1 Q1.3 R2.2 U1.9 | length 726.6
  Top Layer w6: C4.1 R2.2 v1(401.91,961.01) U1.9 ; v1(655.28,607.14) Q1.3
  Bottom Layer w6: v1(401.91,961.01) 386.55,945.66 386.55,751.32 530.73,607.14 v1(655.28,607.14)
GND: C1.2 C3.2 C4.2 C5.2 C6.2 C7.2 C8.2 C9.2 C10.2 C11.2 D2.1 H1.4 H1.5 J1.1 J1.A1 J1.A12 J1.B1 J1.B12 J2. Q3.2 Q4.2 Q4.3 R8.2 R9.2 R10.2 R11.2 R13.2 R14.2 R16.2 R17.2 R21.2 R22.1 R27.2 S1.3 S1.4 S2.3 S2.4 S3.4 S4.3 S4.4 S5.3 S5.4 TP4.1 U1.49 U2.2 U2.25 U3.1 U3.2 U3.3 U3.6 U3.7 U4.2 U5.2 U6.2 X1.1 X1.5 X1.6 X1.12 | length 2498.9
  Top Layer w6: v1(25,1254.67) 59.13,1288.81 R8.2 ; v1(186.45,224.67) R13.2 ; C8.2@238.55,414.22 C8.2 C8.2@263.1,419.81 ; v1(248.28,1039.81) C5.2 ; v1(274.14,294.47) R16.2 ; v1(305.84,926.01) C4.2 ; v1(321.55,756.32) 341.55,756.32 361.55,736.32 R10.2 389.43,713.44 409.12,693.75 474.95,693.75 U2.25 ; R11.2 v1(385.57,595.33) ; v1(489.14,329.7) C7.2 ; C3.2 v1(541.01,521.32) ; v1(531.84,64.67) S3.4@552.17,85 ; R21.2 v1(626.9,371.19) ; v1(638.39,474.7) C11.2 ; Q4.3 Q4.3@823.79,431.01 ; v1(880.24,801.22) R17.2 ; C10.2 v1(981.35,1034.22) ; Q3.2 v1(951.9,981.03) ; C10.2@959.02,1041.23 959.02,1086.23 C9.2 ; D2.1 v1(1044.35,41.82) ; R9.2 v1(1056.45,1104.67) ; R14.2 v1(1061.45,204.67) ; U3.3 1028.39,599.38 1024.02,603.75 1024.02,619.07 ; U3.2 1024.02,619.07 ; U3.1 v1(1024.02,638.75) 1024.02,619.07 ; v1(1072.84,896.82) C6.2 ; U3.6 1116.9,552.27 1120.41,548.75 1126.68,548.75 ; C1.2 1128.71,546.72 1126.68,548.75 ; U3.7 1136.58,552.4 1132.94,548.75 1126.68,548.75
  Top Layer w8: S3.4@552.17,85 R27.2
  Top Layer w10: v1(1128.71,494.07) C1.2
  Top Layer w12: v1(174.1,414.22) C8.2@238.55,414.22 ; J1.A1@243.39,792.22 J1.1@243.39,833.54 ; J1.1@246.39,494.54 J1.B1@246.39,536.54 ; C8.2@263.1,419.81 291.29,391.62 U5.2 ; H1.4 v1(343.73,1193.81) ; U6.2 v1(774.82,369.22) ; Q4.2 855.9,457.02 861.91,451.01 861.91,443.51 ; Q4.3@823.79,431.01 856.91,431.01 861.91,436.01 861.91,443.51 ; R22.1 v1(854.14,339.07) ; v1(884.41,443.51) 861.91,443.51 ; U4.2 v1(1087.72,806.82)
  Bottom Layer w6: v1(343.73,1193.81) 409.91,1193.81 463.27,1140.44 X1.12 ; X1.6 628.62,1078.55 634.55,1084.47 v1(656.18,1084.47) X1.5 ; X1.1@766.27,981.03 v1(951.9,981.03)
  other v1: 212.95,29.67 531.84,29.67 212.95,64.67 24.35,74.67 1216.45,74.67 212.95,99.67 531.84,99.67 647.61,119.22 647.61,154.22 647.61,189.22 777.53,189.22 24.35,354.67 1216.45,354.67 25,974.67 1216.45,974.67 574.27,1080.19 1216.45,1254.67 174.43,1288.81 394.91,1288.81
GREEN: R24.2 U1.34 | length 515.6
  Top Layer w6: U1.34 778.39,1079.12 811,1046.51 811,812.14 878.16,744.98 R24.2
INT1: U1.13 U3.4 | length 1363.5
  Top Layer w6: v1(359.98,464.97) 534.98,464.97 594.98,524.97 789.98,524.97 811.29,503.66 916.95,503.66 936.95,483.66 980.29,483.66 1022.53,525.9 1022.53,573.08 1029.14,579.7 U3.4 ; v1(360.94,811.13) 402.37,811.13 472.92,881.68 U1.13
  Bottom Layer w6: v1@360.94,465.94 v1(359.98,464.97) 340.57,484.39 340.57,620.33 360.94,640.7 v1(360.94,811.13)
IO0: Q1.6 R3.2 U1.23 | length 276.6
  Top Layer w6: U1.23 709.03,854.13 741.91,821.26 741.91,768.05 789.1,720.85 R3.2 Q1.6
LCD_BL: R15.1 U1.15 | length 448.3
  Top Layer w6: v1(551.55,846.32) U1.15 ; R15.1 v1(912.53,875.62)
  Bottom Layer w6: v1(551.55,846.32) 576.55,846.32 581.67,851.43 705.79,851.43 716,841.22 776.23,841.22 810.62,875.62 v1(912.53,875.62)
NetA1_1: A1.1 C2.2 | length 287.2
  Top Layer w8: C2.2 424.91,1203.81 cw(c473.19,1203.81) 439.05,1237.95 445.04,1243.93 cw(c515.75,1173.22) 515.75,1273.22 A1.1
NetC2_1: C2.1 U1.2 | length 67
  Top Layer w8: C2.1 U1.2
NetC8_1: C8.1 S3.1 U5.1 U5.3 | length 701.1
  Top Layer w6: C8.1 C8.1@254.14,354.7 ; S3.1@461.32,151.82 461.45,151.69 S3.1
  Top Layer w15: v1(244.14,319.65) C8.1 ; C8.1@254.14,354.7 359.14,354.7 369.14,364.7 369.14,419.7 359.81,429.03 U5.1 ; S3.1@461.32,151.82 v1(491.32,151.82)
  Bottom Layer w15: v1(244.14,319.65) 244.14,225 317.32,151.82 v1(491.32,151.82)
NetC12_1: C12.1 R19.1 U7.5 | length 102.6
  Top Layer w15: R19.1 C12.1 U7.5
NetC12_2: C12.2 J2.2 Q4.6 Q4.7 U7.6 | length 891.8
  Top Layer w6: 1117.41,431.43 1119.14,429.7
  Top Layer w7: C12.2 983.32,163.39 U7.6
  Top Layer w15: v1(663.28,239.85) J2.2 ; v1(981.75,132.14) C12.2 ; U7.6 1023.32,219.46 1046,242.14 1046,322.14 1119.14,395.28 1119.14,429.7 1119.14,449.7 1111.82,457.02 Q4.7 ; Q4.6 1117.41,431.43
  Bottom Layer w15: v1(663.28,239.85) 771,132.14 v1(981.75,132.14)
NetD1_1: D1.1 Q2.2 S3.2 | length 163.4
  Top Layer w7: D1.1 cw(c399.17,217.39) D1.1@402.39,217.39
  Top Layer w15: D1.1 Q2.2 ; S3.2 D1.1@402.39,217.39
NetD2_2: D2.2 R18.1 | length 50
  Top Layer w7: D2.2 R18.1
NetD3_1: D3.1 R20.1 | length 50
  Top Layer w7: D3.1 R20.1
NetD4_2: D4.2 R25.1 | length 45
  Top Layer w7: R25.1 D4.2
NetD4_3: D4.3 R24.1 | length 106.9
  Top Layer w6: R24.1 978.29,634.22 993.04,619.47 D4.3
NetD4_4: D4.4 R23.1 | length 154.6
  Top Layer w6: R23.1 917.53,533.5 942.95,508.08 979.71,508.08 993.04,521.41 D4.4
NetF1_2: F1.2 J1.A4 J1.A9 J1.B4 J1.B9 | length 478.1
  Top Layer w7: J1.B4 183.78,573.52 164.18,593.12 164.18,733.12 185.88,754.82 J1.B9
  Top Layer w10: J1.A9@251.2,566.32 326.2,566.32 331.2,561.32 F1.2
NetJ1_A5: J1.A5 R10.1 | length 57.6
  Top Layer w7: J1.A5 R10.1
NetJ1_B5: J1.B5 R11.1 | length 57.6
  Top Layer w7: J1.B5 R11.1
NetQ1_2: Q1.2 R6.1 | length 104.1
  Top Layer w6: Q1.2 687.7,659.81 702.53,644.99 R6.1
NetQ1_5: Q1.5 R7.1 | length 99.3
  Top Layer w6: R7.1 694.65,682.86 717.7,659.81 Q1.5
NetQ3_1: Q3.1 R15.2 R17.1 | length 98
  Top Layer w6: R17.1@951.9,801.22 R15.2 Q3.1
NetQ3_3: Q3.3 R12.2 | length 80.9
  Top Layer w6: R12.2 876.27,923.99 Q3.3
NetQ4_1: Q4.1 Q4.8 | length 266.9
  Top Layer w12: Q4.1 908,482.61 931.95,458.66 990.29,458.66 1014.24,482.61 Q4.8
NetQ4_4: Q4.4 U7.3 | length 160.4
  Top Layer w12: Q4.4 893,405.84 909.32,389.52 U7.3
NetQ4_5: Q4.5 U7.1 | length 155.3
  Top Layer w12: U7.1 983.32,378.88 1010.28,405.84 Q4.5
NetR1_2: R1.2 U3.12 | length 58.1
  Top Layer w6: U3.12 1136.58,703.91 R1.2
NetR12_1: R12.1 X1.2 | length 408.2
  Top Layer w6: R12.1 v1(836.9,1054.97)
  Bottom Layer w6: X1.2 738.86,1063.78 745.05,1069.97 821.9,1069.97 v1(836.9,1054.97)
NetR21_1: R21.1 U6.5 | length 47.4
  Top Layer w6: R21.1 U6.5
NetR22_2: R22.2 U7.2 | length 137.4
  Top Layer w12: R22.2 933.51,269.07 946.32,281.87 U7.2
NetU2_5: U2.5 U2.6 | length 60.2
  Top Layer w6: U2.6 410.36,615.01 406.85,618.53 406.85,631.18 410.36,634.7 U2.5
RED: R25.2 U1.29 | length 473.8
  Top Layer w6: U1.29 786.82,980.7 794,973.51 794,798.22 849.1,743.12 849.1,603.41 858.29,594.22 R25.2
RST: U1.39 X1.11 | length 601.3
  Top Layer w6: U1.39 689.74,1139.16 689.74,1153.11 702.95,1166.32 v1(761.85,1166.32)
  Bottom Layer w6: X1.11 490.83,1140.95 588.54,1238.66 689.5,1238.66 v1(761.85,1166.32)
RTS: Q1.4 R6.2 U2.19 | length 447.2
  Top Layer w6: U2.19 598.62,739.52 609.1,729.03 609.1,559.03 619.1,549.03 733.91,549.03 741.9,557.02 R6.2 Q1.4
RXD: U1.40 U2.21 | length 1381.6
  Top Layer w6: v1(504.1,774.03) 514.32,763.82 U2.21 ; U1.40 669.66,1156.03 707.85,1194.22 968,1194.22 1009.98,1152.24 1009.98,877.2 986,853.22 v1(986,766.22)
  Bottom Layer w6: v1(504.1,774.03) 566.82,711.32 672.42,711.32 726.32,765.22 833.39,765.22 864.14,734.47 954.25,734.47 v1(986,766.22)
SCL: H1.1 R5.1 TP1.1 U1.17 U3.13 U4.6 | length 2023.8
  Top Layer w6: v1(225.62,1084.59) H1.1 ; v1(319.91,843.81) 319.91,812.96 351.55,781.32 452.55,781.32 474.55,803.32 474.55,809.32 v1(491.55,826.32) 521.55,826.32 526.55,821.32 566.38,821.32 590.92,845.85 U1.17 ; R5.1 984.1,729.22 v1(1004.1,709.22) ; U3.13 1116.9,668.05 1101.2,683.76 1101.2,731.32 1111.2,741.32 1201.2,741.32 1211.2,751.32 1211.2,836.32 1203.29,844.22 U4.6 1180.91,881.85 1199.1,900.03 v1(1199.1,904.22)
  Bottom Layer w6: v1(225.62,1084.59) 258.28,1084.59 336.55,1006.32 336.55,860.45 v1(319.91,843.81) ; v1(491.55,826.32) 475.06,809.83 475.06,757.81 541.55,691.32 677.42,691.32 732.32,746.22 812.39,746.22 849.39,709.22 v1(1004.1,709.22) 1104.23,709.22 v1(1135.98,740.97) v1@1131.21,740.97
SDA: H1.2 R4.1 TP2.1 U1.20 U3.14 U4.1 | length 2151.3
  Top Layer w6: H1.2 v1(264.99,1193.81) ; U1.20 649.98,853.19 671.85,831.32 v1(671.85,801.32) ; R4.1 1081.2,679.22 ; U4.1 v1(1114.41,844.22) ; U3.14 1097.21,663.21 1081.2,679.22 ; v1@1114.41,843.51 1114.41,769.53 1081.2,736.32 1081.2,679.22
  Bottom Layer w6: v1(264.99,1193.81) 264.99,1148.73 434.91,978.81 434.91,872.96 451.55,856.32 501.55,856.32 606.55,751.32 652.42,751.32 671.23,770.13 671.23,801.32 v1(671.85,801.32) 801.2,801.32 829.1,829.22 1000.12,829.22 1015.12,844.22 v1(1114.41,844.22) 1170.57,788.06 1170.57,720.33 1140.57,690.33 1140.57,630.33 1199.1,571.79 v1(1199.1,474.22)
SPI_CLK: U1.35 X1.9 | length 633.5
  Top Layer w6: U1.35 824.34,1098.81 v1(841.85,1116.32)
  Bottom Layer w6: X1.9@546.27,966.19 546.27,1139.64 612.29,1205.66 645.23,1205.66 734.58,1116.32 v1(841.85,1116.32)
SPI_MOSI: U1.36 X1.10 | length 697.4
  Top Layer w6: U1.36 799.02,1118.49 v1(846.85,1166.32)
  Bottom Layer w6: X1.10 518.39,1143.51 597.54,1222.66 663.23,1222.66 749.58,1136.32 816.85,1136.32 v1(846.85,1166.32)
TFT_CS: U1.24 X1.8 | length 310.5
  Top Layer w6: U1.24 728.72,868.5 731,866.22 v1(751,866.22)
  Bottom Layer w6: X1.8 573.5,883.95 582.13,875.33 716.9,875.33 726,866.22 v1(751,866.22)
TXD: U1.41 U2.20 | length 1377.8
  Top Layer w6: U2.20 534,763.94 v1(544.1,774.03) ; U1.41 649.98,1160.31 700.98,1211.32 978.64,1211.32 1027,1162.95 1027,857.22 1019.1,849.33 v1@1019.1,796.22
  Bottom Layer w6: v1(544.1,774.03) 586.82,731.32 667.42,731.32 719.32,783.22 850.39,783.22 862.39,771.22 890.89,771.22 915.89,796.22 v1(1019,796.22)
VBAT: C11.1 J2.1 Q2.3 R19.2 R26.1 U6.3 | length 752
  Top Layer w6: R26.1 Q2.3@555.63,245.26 ; C11.1 C11.1@734.19,474.65
  Top Layer w15: Q2.3 555.63,245.26 609.71,245.26 654.14,289.7 689.14,289.7 ; J2.1 v1(732.25,289.7) 689.14,289.7 ; C11.1@734.19,474.65 U6.3 696.07,406.62 689.14,399.7 689.14,289.7 ; R19.2 v1(861.95,191.5)
  Bottom Layer w15: v1(732.25,289.7) 830.44,191.5 v1(861.95,191.5)
VUSB: C3.1 D1.2 D3.2 F1.1 Q2.1 R16.1 R18.2 U2.7 U2.8 U6.4 | length 1834.4
  Top Layer w6: 455.26,566.32 474.95,566.32 ; C3.1 474.95,566.32 ; U2.8 474.95,566.32 ; 480,293.03 481.45,294.47 ; v1(836.32,41.82) D3.2 ; R18.2 v1(1045.69,91.82)
  Top Layer w10: F1.1 v1(406,566.32) 455.26,566.32 U2.7
  Top Layer w15: D1.2 321.45,219.67 339.14,237.36 R16.1 481.45,294.47 509.47,294.47 554.14,339.14 554.14,397.84 562.93,406.62 U6.4 ; Q2.1 480,293.03
  Bottom Layer w6: v1(406,295.14) 659.32,41.82 v1(836.32,41.82) 911.32,41.82 961.32,91.82 v1(1045.69,91.82)
  Bottom Layer w15: v1(406,295.14) v1(406,566.32)
pads on no net: A1. J1. J1.A8 J1.B8 S1. S2. S3. S3.3 S4. S5. U1.5 U1.6 U1.7 U1.8 U1.16 U1.21 U1.25 U1.26 U1.27 U1.30 U1.31 U1.32 U1.33 U1.38 U1.44 U1.45 U1.47 U1.48 U2.1 U2.9 U2.10 U2.11 U2.12 U2.13 U2.14 U2.15 U2.16 U2.17 U2.18 U2.22 U2.24 U3.9 U3.10 U3.11 U4.3 U4.4 U5.4 U7.4

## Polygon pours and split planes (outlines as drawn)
GND on Layer 1 (split plane): 1195.69,1308.85 1200.27,1307.75 1204.62,1305.95 1208.63,1303.49 1212.21,1300.43 1215.27,1296.85 1217.72,1292.84 1219.53,1288.49 1220.62,1283.91 1220.94,1279.88 1220.9,1279.5 1220.9,1279.27 1220.91,1279.25 1220.9,1279.22 1220.9,50.43 1220.96,49.87 1220.62,45.58 1219.51,40.96 1217.69,36.56 1215.2,32.5 1212.11,28.89 1208.5,25.8 1204.44,23.31 1200.04,21.49 1195.42,20.38 1191.31,20.06 1190.89,20.1 50.1,20.1 49.55,20.04 45.31,20.38 40.73,21.48 36.38,23.28 32.37,25.74 28.79,28.79 25.74,32.37 23.28,36.38 21.48,40.73 20.38,45.31 20.04,49.62 20.06,49.87 20.09,49.87 20.08,50 20.1,50.22 20.1,1279.12 20.04,1279.67 20.38,1283.92 21.48,1288.49 23.28,1292.84 25.74,1296.85 28.79,1300.43 32.37,1303.49 36.38,1305.95 40.73,1307.75 45.31,1308.85 49.36,1309.17 49.75,1309.13 49.98,1309.13 49.99,1309.13 50,1309.13 529.91,1309.13 529.91,1199.22 1084.91,1199.22 1084.91,1309.13 1190.9,1309.13 1191.45,1309.18
+3.3V on Layer 2 (split plane): 1195.69,1308.85 1200.27,1307.75 1204.62,1305.95 1208.63,1303.49 1212.21,1300.43 1215.27,1296.85 1217.72,1292.84 1219.53,1288.49 1220.62,1283.91 1220.94,1279.88 1220.9,1279.5 1220.9,1279.27 1220.91,1279.25 1220.9,1279.22 1220.9,50.43 1220.96,49.87 1220.62,45.58 1219.51,40.96 1217.69,36.56 1215.2,32.5 1212.11,28.89 1208.5,25.8 1204.44,23.31 1200.04,21.49 1195.42,20.38 1191.31,20.06 1190.89,20.1 50.1,20.1 49.55,20.04 45.31,20.38 40.73,21.48 36.38,23.28 32.37,25.74 28.79,28.79 25.74,32.37 23.28,36.38 21.48,40.73 20.38,45.31 20.04,49.62 20.06,49.87 20.09,49.87 20.08,50 20.1,50.22 20.1,1279.12 20.04,1279.67 20.38,1283.92 21.48,1288.49 23.28,1292.84 25.74,1296.85 28.79,1300.43 32.37,1303.49 36.38,1305.95 40.73,1307.75 45.31,1308.85 49.36,1309.17 49.75,1309.13 49.98,1309.13 49.99,1309.13 50,1309.13 529.91,1309.13 529.91,1199.22 1084.91,1199.22 1084.91,1309.13 1190.9,1309.13 1191.45,1309.18

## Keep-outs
Keep-Out Layer:
  lines w10: 0.1,110.22 1,311.22 ; 1,396.22 1,936.22 ; 1,1011.22 1,1216.22 ; 2.02,1293.62 cw(c49.9,1279.22) 50.01,1329.22 1190.9,1329.22 cw(c1191,1279.22) 1238.88,1293.62 ; 2.12,35.61 ccw(c50,50) 50.1,0 174.1,0 ; 249.1,-0.78 494.1,-0.78 ; 569.1,0 1190.89,0 ccw(c1190.99,50) 1238.88,35.61 ; 1241,109.22 1241,319.22 ; 1241,394.22 1241,939.22 ; 1241,1011.22 1241,1216.22

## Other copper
Top Layer:
  text "1" at 58,651 h40
Bottom Layer:
  text "4" at 78,651 h40
Layer 1 (plane layer: these items are gaps in the copper):
  pour cut-out: 364.18,1209.07 364.18,1074.07 484.18,1074.07 484.18,1209.07
  pour cut-out: 529.91,1329.22 529.91,1199.22 1084.91,1199.22 1084.91,1329.22
  text "2" at 50,651 h40
Layer 2 (plane layer: these items are gaps in the copper):
  pour cut-out: 364.18,1209.07 364.18,1074.07 484.18,1074.07 484.18,1209.07
  pour cut-out: 529.91,1329.22 529.91,1199.22 1084.91,1199.22 1084.91,1329.22
  text "3" at 50,651 h40

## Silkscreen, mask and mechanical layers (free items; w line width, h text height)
Top Overlay:
  text "ezDisplay2" at 587,1173.66 h35
  text "Wifi" at 452,1172 h35
  text "R1.2" at 942,1172 h35
  text "SCL" at 1081.1,931.22 h35
  text "+3.3v" at 146.91,920.81 h35
  text "SDA" at 1124.1,399.22 h35
  text "GND" at 41.1,396.22 h35
Bottom Overlay:
  drawing of 573 lines, arcs and shapes, not listed
  text "@mikerankin" at 748.5,202 h35
Mechanical 1:
  lines w10: 0,49.78 ccw(c50,50) 50.1,0 1190.89,0 ccw(c1190.67,50.33) 1241,50.43 1241,1279.22 ; 0,50.22 0,1279.12 cw(c50,1279.22) 49.78,1329.22 ; 50,1329.22 1190.9,1329.22 cw(c1191,1279.22) 1241,1279.44
Mechanical 5:
  lines w5: 1059,657 1059,561 1175,561 1175,658 1060,658 ; 635,100 635,205 790,205 790,100 635,100 ; 860,385 860,504 1032,504 1032,385 860,385
  text "J2" at 702,145 h15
